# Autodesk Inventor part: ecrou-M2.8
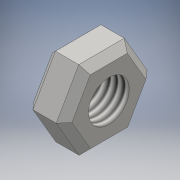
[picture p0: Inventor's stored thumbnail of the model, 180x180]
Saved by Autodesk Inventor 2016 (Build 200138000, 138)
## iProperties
Created: 2018-03
Part Number: ecrou-M2.8
Material: Générique
Document SubType Name: Modeling
Designer: Bruno
Density: 1 g/cm^3
Appearance: Par défaut
Author: Bruno
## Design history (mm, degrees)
sketch "Esquisse1"
  geometry: L1 (-1.547, -2.707)-(-3.118, -0.014); L2 (-3.118, -0.014)-(-1.571, 2.693); L3 (-1.571, 2.693)-(1.547, 2.707); L4 (1.547, 2.707)-(3.118, 0.014); L5 (3.118, 0.014)-(1.571, -2.693); L6 (1.571, -2.693)-(-1.547, -2.707); C1 r 1.4 at (0, 0); 2 further points
  constraints: 12 end point, 2 coincident, 1 centre point, 13 other
  dimensions: "d0" = 2.8 diameter of C1; "d1" = 5.4 distance between parallel lines of L6 L3
extrude "Extrusion1" new body sketch "Esquisse1" distance "d2" = 2.6; taper "d3" = 0 deg
feature "Filetage1" dims "d7" = 10, "d8" = 0
chamfer "Chanfrein3" distance "d12" = 0.5; stored, may be unused: second distance "d13" = 2, angle "d14" = 45 deg
node "Solide1"
